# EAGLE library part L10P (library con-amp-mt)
AMP MT CONNECTOR
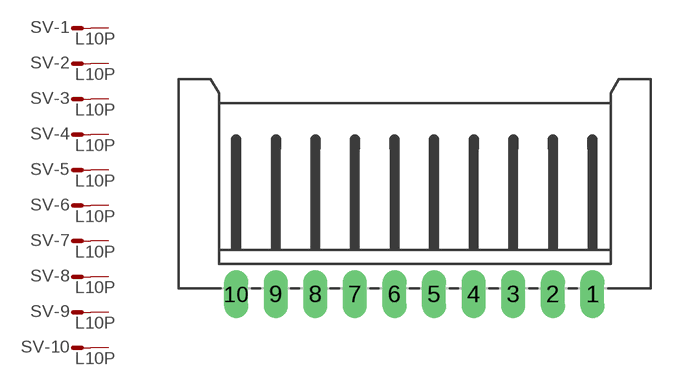
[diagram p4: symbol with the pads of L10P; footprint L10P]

Designator prefix SV; gates -1=M -2=M -3=M -4=M -5=M -6=M -7=M -8=M -9=M -10=M

## L10P (OC_FARNELL: unknown; OC_NEWARK: unknown)  [L10P]
1  -1:S  pas
2  -2:S  pas
3  -3:S  pas
4  -4:S  pas
5  -5:S  pas
6  -6:S  pas
7  -7:S  pas
8  -8:S  pas
9  -9:S  pas
10  -10:S  pas

## Footprint L10P (pad centres in mm)
AMP MT CONNECTOR
drill 1.016 long: 1 11.25,-6.25; 2 8.75,-6.25; 3 6.25,-6.25; 4 3.75,-6.25; 5 1.25,-6.25; 6 -1.25,-6.25; 7 -3.75,-6.25; 8 -6.25,-6.25; 9 -8.75,-6.25; 10 -11.25,-6.25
